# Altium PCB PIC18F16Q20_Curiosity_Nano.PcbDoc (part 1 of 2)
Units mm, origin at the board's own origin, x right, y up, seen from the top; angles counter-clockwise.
Board outline 50.8 x 20.32 mm, 4 copper layers (Top Layer, Gnd Plane, Pwr Plane, Bottom Layer), stack 1.574 mm thick; 77 components, 73 nets, 345 pads, 157 vias.
Unrouted connection lines stored in the file: 1.
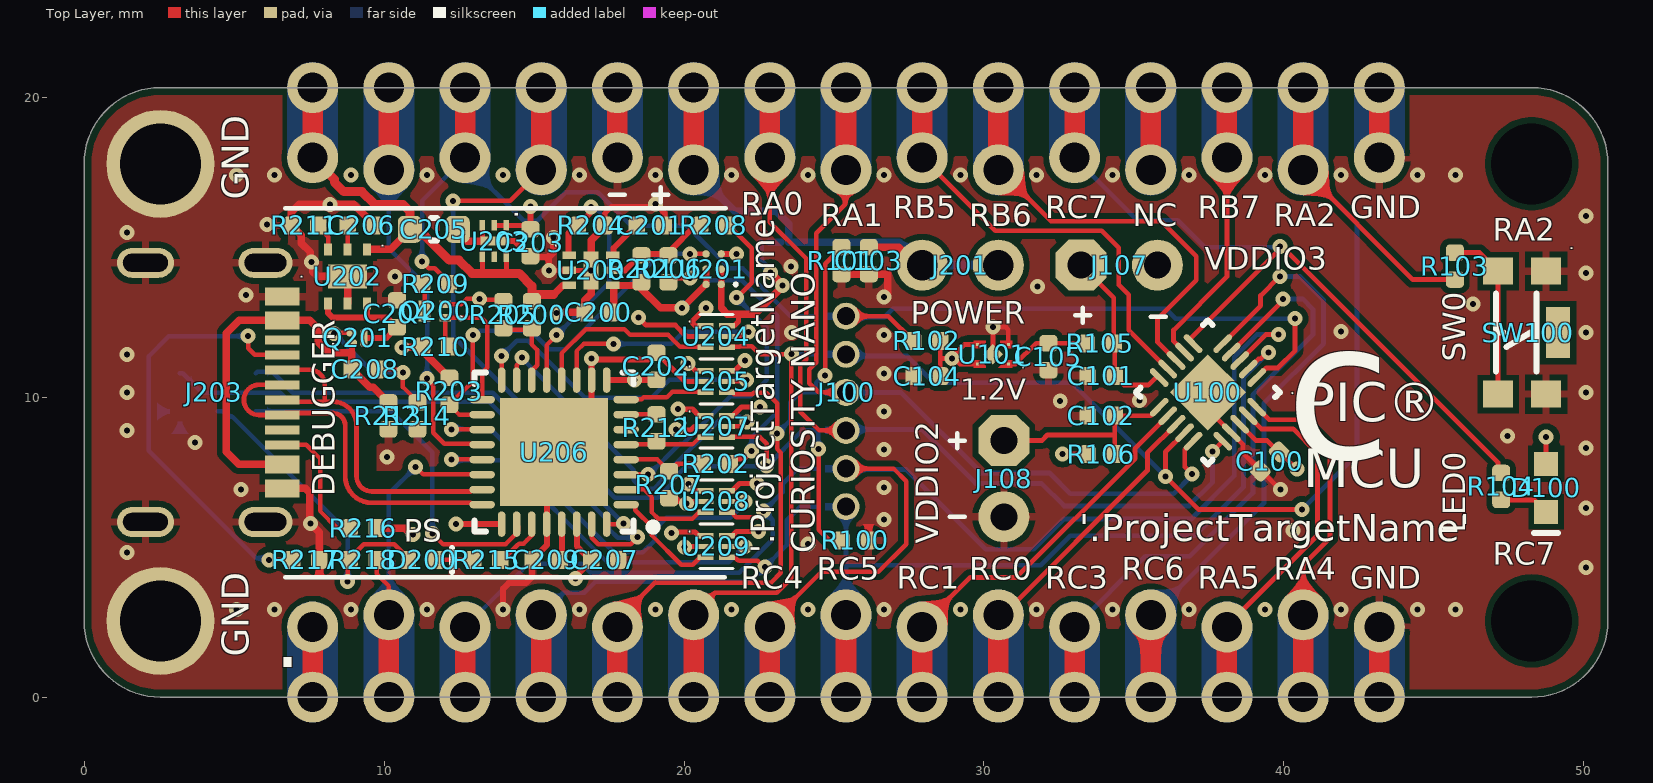
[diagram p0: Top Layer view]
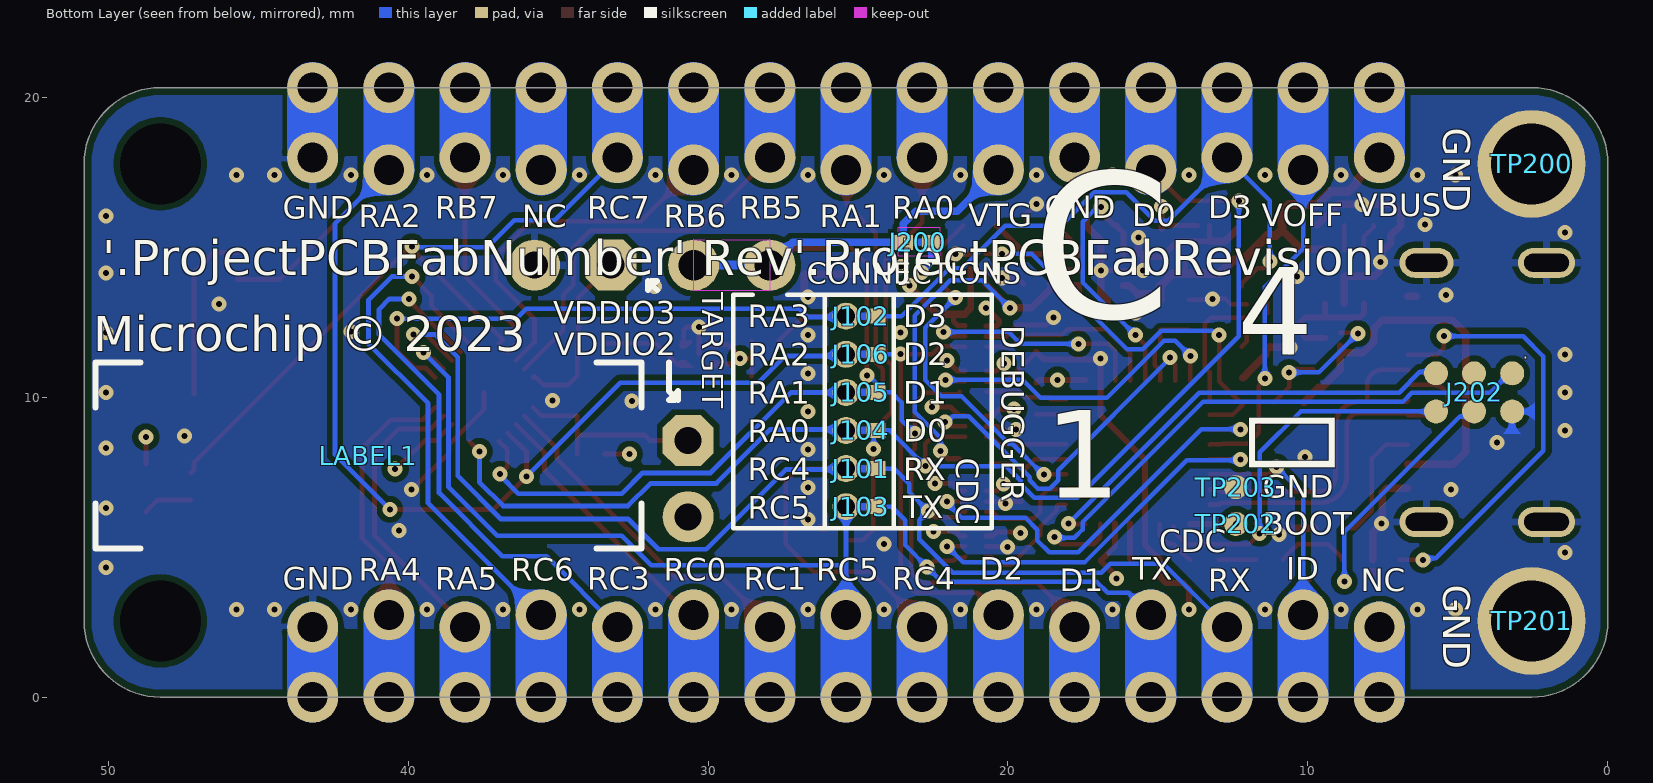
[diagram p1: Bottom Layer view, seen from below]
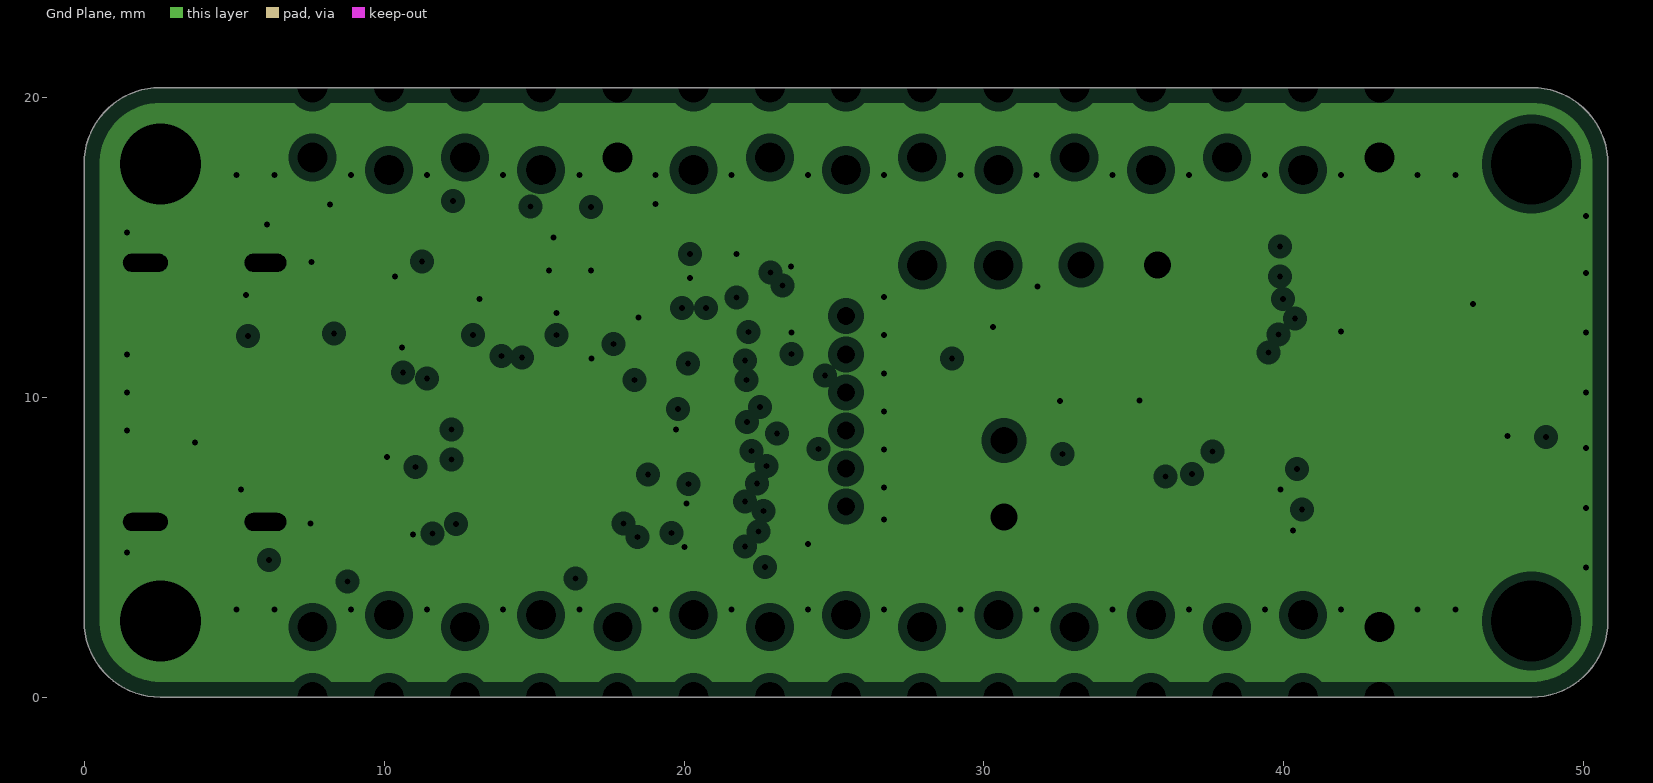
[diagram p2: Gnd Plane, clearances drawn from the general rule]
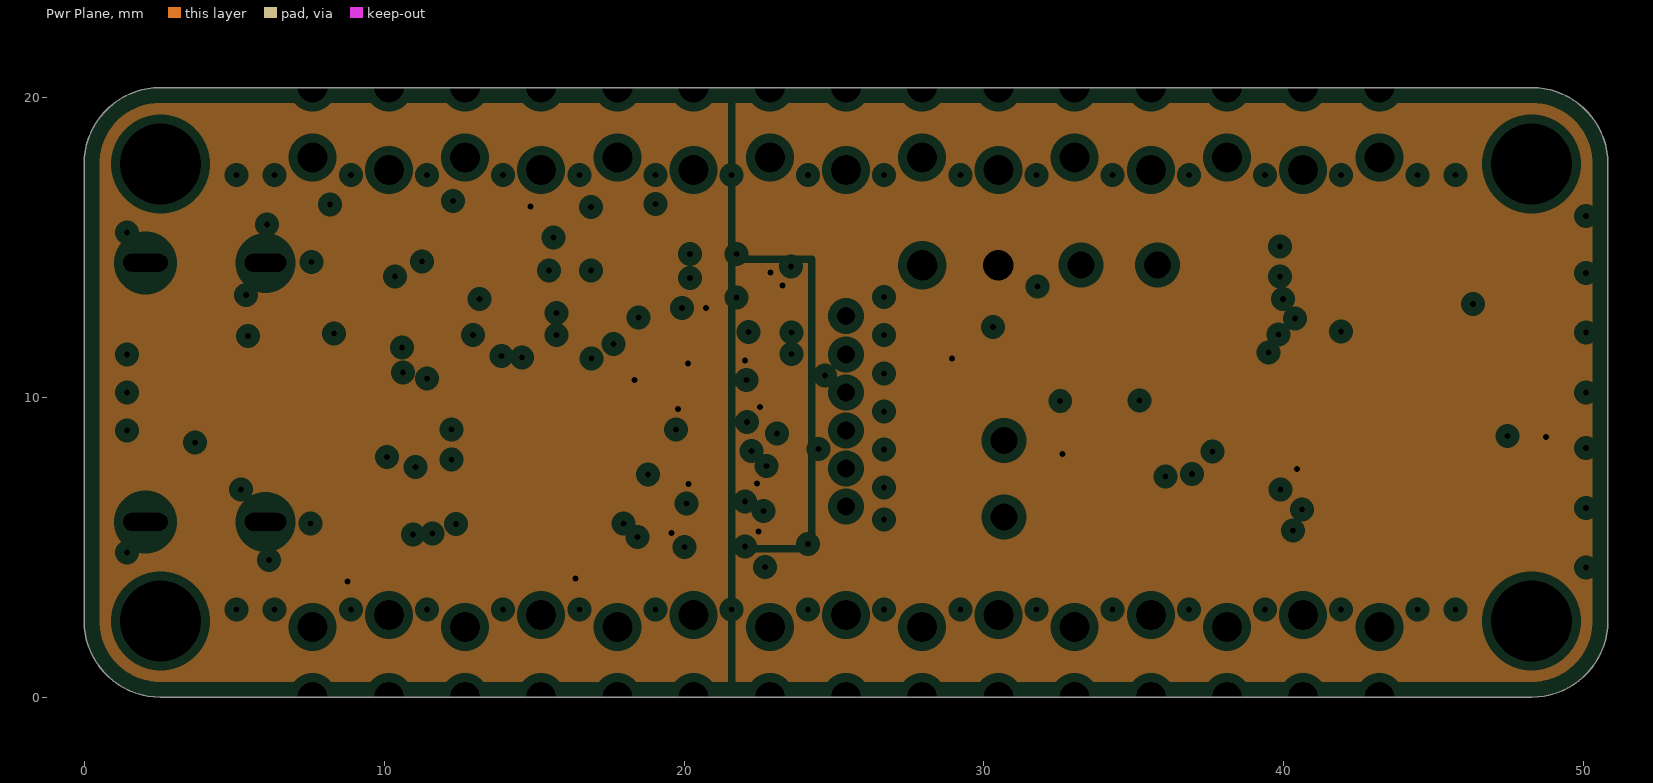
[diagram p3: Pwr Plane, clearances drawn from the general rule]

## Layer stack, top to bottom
Top Solder: solder mask 0.01, Solder Resist, Dk 3.5
Top Layer: signal copper 0.035
Dielectric 1: prepreg 0.1168, PP-016, Dk 4.4
Gnd Plane: plane copper 0.035, net GND
Dielectric2: core 1.2, FR-4, Dk 4.2
Pwr Plane: plane copper 0.035, net (Multiple Nets)
Dielectric 3: prepreg 0.1168, PP-016, Dk 4.4
Bottom Layer: signal copper 0.035
Bottom Solder: solder mask 0.01, Solder Resist, Dk 3.5

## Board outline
0,2.54 0,17.78 cw(c2.54,17.78) 2.54,20.32 48.26,20.32 cw(c48.26,17.78) 50.8,17.78 50.8,2.54 cw(c48.26,2.54) 48.26,0 2.54,0 cw(c2.54,2.54)

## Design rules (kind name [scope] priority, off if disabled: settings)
AcuteAngle [All] p1: minimum=8.00000000000000E+0001 checktracksonly=FALSE
AssemblyTestPointUsage [All] p1: valid=2 allowmultiple=TRUE
AssemblyTestpoint CNANO_Testpoints [HasCompParameterValue('MCHP-ID','CON2115') Or HasCompParameterValue('MCHP-ID','CON2119') Or HasCompParameterValue('MCHP-ID','CON2120')] p1: testpointundercomponent=TRUE minsize=0.8 maxsize=2.54 preferedsize=0.8 minholesize=0 maxholesize=1.27 preferedholesize=0.25 testpointgrid=0.025 usegrid=FALSE gridtolerance=0 allowsidebottom=TRUE minspacing=1.27
AssemblyTestpoint [All] p2: testpointundercomponent=FALSE minsize=0.8 maxsize=2.54 preferedsize=0.8 minholesize=0 maxholesize=1.27 preferedholesize=0.25 testpointgrid=0.025 usegrid=FALSE gridtolerance=0 allowsidebottom=TRUE minspacing=1.27 compbodyclearance=1.27
BoardOutlineClearance BoardOutlineClearance_edge_connector [InComponent('J100')] p1: gap=0 ignorepadtopadclearanceinfootprint=FALSE
BoardOutlineClearance BoardOutlineClearance_LAYERNAME [IsText and (X1 >= 100) and (Y1 <= -60)] p2: gap=0 ignorepadtopadclearanceinfootprint=FALSE
BoardOutlineClearance [All] p3: gap=0.25 ignorepadtopadclearanceinfootprint=FALSE
Clearance Clearance_Poly_Impedance [IsRegion vs InDifferentialPairClass('All Differential Pairs')] p1: gap=0.6 ignorepadtopadclearanceinfootprint=FALSE
Clearance Clearance_Poly [InPoly] p2: gap=0.2 ignorepadtopadclearanceinfootprint=FALSE
Clearance [All] p3: gap=0.15 ignorepadtopadclearanceinfootprint=FALSE except(0.3: Arc-Hole Track-Hole SMDPad-Hole THPad-Hole Via-Hole Fill-Hole Poly-Hole Region-Hole Text-Hole)
ComponentClearance ComponentClearance_EDGE [InComponent('J100')] p1: gap=0 collisioncheckmode=3 verticalgap=0 showdistances=FALSE
ComponentClearance [All] p2: gap=0.254 collisioncheckmode=3 verticalgap=0.254 showdistances=TRUE donotcheckwithout3dbody=TRUE
DiffPairsRouting [All] p1: maxlimit=0.22 minlimit=0.22 mostfreqgap=0.22 toplayer_minwidth=0.16 toplayer_maxwidth=0.16 toplayer_prefwidth=0.16 bottomlayer_minwidth=0.16 bottomlayer_maxwidth=0.16 bottomlayer_prefwidth=0.16 maxuncoupledlength=5
FabricationTestPointUsage TestPointUsage [All] p1 off: valid=2 allowmultiple=TRUE
FabricationTestpoint Testpoint [All] p1 off: side=2 testpointundercomponent=TRUE minsize=0.8 maxsize=2.54 preferedsize=0.8 minholesize=0 maxholesize=1.27 preferedholesize=0.25 testpointgrid=0 allowsidebottom=TRUE usegrid=FALSE gridtolerance=0 minspacing=1.27
HoleSize [All] p1: absolutevalues=TRUE maxlimit=6.2 minlimit=0.2 maxpercent=80.000 minpercent=20.000
HoleToHoleClearance [All] p1: gap=0.3 allowstackedmicrovias=FALSE
MinimumAnnularRing [All] p1: minimumring=0.15
MinimumSolderMaskSliver LevelShifters [HasCompParameterValue('MCHP-ID','IC1665')] p1: minsoldermaskwidth=0.075
MinimumSolderMaskSliver [All] p2: minsoldermaskwidth=0.08
NetAntennae [Not IsTestpoint] p1: netantennaetolerance=0
PlaneClearance [All] p1: clearance=0.3
PlaneConnect PlaneConnect_MountingHoles [HasPad('TP200-1') OR HasPad('TP201-1')] p1: planeconnectstyle=Direct reliefexpansion=0.508 reliefentries=4 reliefconductorwidth=0.254 reliefairgap=0.254
PlaneConnect [All] p2: pad.planeconnectstyle=Relief pad.reliefexpansion=0.25 pad.reliefentries=4 pad.reliefconductorwidth=0.25 pad.reliefairgap=0.25 via.planeconnectstyle=Direct via.reliefexpansion=0.508 via.reliefentries=4 via.reliefconductorwidth=0.254 via.reliefairgap=0.254
PolygonConnect PolygonConnect_Special [HasPad('TP200-1') OR HasPad('TP201-1') OR HasPad('TP203-1')] p1: connectstyle=Direct reliefconductorwidth=0.254 reliefentries=4 polygonreliefangle="90 Angle" airgapwidth=0.254
PolygonConnect [All] p2: thpad.connectstyle=Relief thpad.reliefconductorwidth=0.254 thpad.reliefentries=4 thpad.polygonreliefangle="90 Angle" thpad.airgapwidth=0.2 smdpad.connectstyle=Relief smdpad.reliefconductorwidth=0.254 smdpad.reliefentries=4 smdpad.polygonreliefangle="90 Angle" smdpad.airgapwidth=0.2 via.connectstyle=Direct via.reliefconductorwidth=0.254 via.reliefentries=4 via.polygonreliefangle="90 Angle" via.airgapwidth=0.2
RoutingVias [All] p1: holewidth=0.25 width=0.55 viastyle="Through Hole" minholewidth=0.2 minwidth=0.5 maxholewidth=0.5 maxwidth=1
SMDNeckDown [All] p1: percent=98.000
SilkToSilkClearance SilkToSilkClearance_Text [IsText] p1: silktosilkclearance=0
SilkToSilkClearance [All] p2: silktosilkclearance=0.1
SilkToSolderMaskClearance SilkscreenOverComponentPads_Soldermask [All] p1: minsilkscreentomaskgap=0.12 clearancetoexposedcopper=FALSE
SilkToSolderMaskClearance SilkscreenOverComponentPads_Copper [All] p2: minsilkscreentomaskgap=0.2 clearancetoexposedcopper=TRUE
SolderMaskExpansion SolderMaskTenting [IsVia AND NOT (IsFabTestpoint OR IsAssyTestpoint)] p1: expansion=-1 istentingtop=FALSE
SolderMaskExpansion [All] p2: expansion=0.06 istentingtop=FALSE
UnRoutedNet [All] p1: checkbadconnections=TRUE
ViasUnderSMD ViasUnderSMD_Testpoint [HasPad('TP202-1') OR HasPad('U200-7')] p1: allowed=TRUE
ViasUnderSMD [All] p2: allowed=FALSE
Width [All] p1: maxlimit=10 minlimit=0.125 preferedwidth=0.15 minimp=50.000000 maximp=50.000000 favimp=50.000000
15 further rules are at their usual default settings.

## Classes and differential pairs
component class PIC18F16Q20_Curiosity_Nano_TopLevel: LABEL1 Test1 Test2 "TEST FIXTURE1"
component class S2: C100 C101 C102 C103 C104 C105 D100 J100 J101 J102 J103 J104 J105 J106 J107 J108 R100 R101 R102 R103 R104 R105 R106 SW100 U100 U101
component class S1: C200 C201 C202 C203 C204 C205 C206 C207 C208 C209 D200 J200 J201 J202 J203 Q200 Q201 R200 R201 R202 R203 R204 R205 R206 R207 R208 R209 R210 R211 R212 R213 R214 R215 R216 R217 R218 TP200 TP201 TP202 TP203 U200 U201 U202 U203 U204 U205 U206 U207 U208 U209
net class Power: GND VCC_EDGE VCC_LEVEL VCC_P3V3 VCC_REGULATOR VCC_VBUS
differential pair USBD: +USBD_P -USBD_N

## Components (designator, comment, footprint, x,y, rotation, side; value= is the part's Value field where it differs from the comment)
C100 "Capacitor NP" CAP_C_0402#1 39.522,7.857 r225 top value=0.1uF
C101 "Capacitor NP" CAP_C_0402#1 33.908,10.713 r180 top value=0.1uF
C102 "Capacitor NP" CAP_C_0402#1 33.917,9.382 r180 top value=0.1uF
C103 "Capacitor NP" CAP_C_0402#1 26.162,14.554 r90 top locked value=2.2uF
C104 "Capacitor NP" CAP_C_0402#2 28.105,10.701 r0 top value=1uF
C105 "Capacitor NP" CAP_C_0402#2 32.149,11.35 r90 top value=1uF
C200 "Capacitor NP" CAP_C_0402#1 17.145,12.827 r0 top locked value=2.2uF
C201 "Capacitor NP" CAP_C_0402#1 18.88,15.725 r0 top locked value=0.1uF
C202 "Capacitor NP" CAP_C_0402#1 19.08,11.025 r270 top locked value=0.1uF
C203 "Capacitor NP" CAP_C_0402#1 14.879,15.15 r90 top locked value=2.2uF
C204 "Capacitor NP" CAP_C_0402#1 10.434,12.777 r270 top locked value=2.2uF
C205 "Capacitor NP" CAP_C_0603 11.658,15.597 r180 top locked value=4.7uF
C206 "Capacitor NP" CAP_C_0402#1 9.235,15.725 r180 top locked value=2200pF
C207 "Capacitor NP" CAP_C_0402#1 17.355,4.575 r0 top locked value=0.1uF
C208 "Capacitor NP" CAP_C_0402#1 9.368,10.931 r180 top locked value=0.1uF
C209 "Capacitor NP" CAP_C_0402#1 15.405,4.575 r0 top locked value=1uF
D100 "LED_yellow" LED_0603_Yellow 48.74,6.975 r270 top value="Yellow LED"
D200 "LED_green" LED_0402_GREEN 11.265,4.575 r0 top locked value="LED SINGLE SML-P12MTT86R YELLOW-GREEN"
J100 "CON EDGE CNANO-30" CON_EDGE_CNANO-30 7.62,10.16 r0 top locked value="EDGE 30P Female CNANO"
J101 "CON JMPR LINK CLOSED" CON_JMPR_0402_PCB_TRACE_LINK_0.9mm_PAD_0.6mm_PTH 24.875,7.62 r0 bottom locked net-tie value="CON JMPR LINK CLOSED_0.9mm TH PAD"
J102 "CON JMPR LINK CLOSED" CON_JMPR_0402_PCB_TRACE_LINK_0.9mm_PAD_0.6mm_PTH 24.875,12.7 r0 bottom locked net-tie value="CON JMPR LINK CLOSED_0.9mm TH PAD"
J103 "CON JMPR LINK CLOSED" CON_JMPR_0402_PCB_TRACE_LINK_0.9mm_PAD_0.6mm_PTH 24.875,6.35 r0 bottom locked net-tie value="CON JMPR LINK CLOSED_0.9mm TH PAD"
J104 "CON JMPR LINK CLOSED" CON_JMPR_0402_PCB_TRACE_LINK_0.9mm_PAD_0.6mm_PTH 24.875,8.89 r0 bottom locked net-tie value="CON JMPR LINK CLOSED_0.9mm TH PAD"
J105 "CON JMPR LINK CLOSED" CON_JMPR_0402_PCB_TRACE_LINK_0.9mm_PAD_0.6mm_PTH 24.875,10.16 r0 bottom locked net-tie value="CON JMPR LINK CLOSED_0.9mm TH PAD"
J106 "CON JMPR LINK CLOSED" CON_JMPR_0402_PCB_TRACE_LINK_0.9mm_PAD_0.6mm_PTH 24.875,11.43 r0 bottom locked net-tie value="CON JMPR LINK CLOSED_0.9mm TH PAD"
J107 "Header 1x2" HDR_M_2.54_1x2 34.512,14.402 r0 top value="HDR-2.54 Male 1x2"
J108 "Header 1x2" HDR_M_2.54_1x2 30.663,7.282 r270 top value="HDR-2.54 Male 1x2"
J200 "CON JMPR LINK CLOSED" CON_JMPR_0402_PCB_TRACE_LINK 23.015,15.162 r0 bottom locked net-tie value="CON 0402 PCB TRACE LINK"
J201 "CON JMPR LINK CLOSED" CON_JMPR_2.54_1x2_TH_PCB_TRACE_LINK 29.21,14.402 r0 top locked net-tie value="CON JMPR 1x2 PCB TRACE LINK"
J202 "TP ARRAY NO BOM" TESTPOINT_ARRAY_2x3_1.27mm_pitch_SMD 4.46,10.16 r0 bottom locked value="TESTPOINT ARRAY 2x3 JTAG"
J203 "CON USB2.0-C RCPT SMD RA KLS KLS1-5409" CON_USB2.0-C_RCPT_SMD_RA_KLS_KLS1-5409 3.4,10.16 r270 top locked value="USB2.0 Type-C FEMALE"
LABEL1 "08-10015" 08-10015 41.325,8.05 r180 bottom locked value="PCBA LABEL 18X6mm"
Q200 "Transistor MOS-N GSD" X1-DFN1006-3 11.69,12.875 r180 top locked value=DMN65D8LFB-7B
Q201 "Transistor MOS-P GSD" LGA-3_GSD_0.7x0.6_CSD25501F3 9.102,11.975 r0 top locked value=CSD25501F3
R100 "Resistor" RES_C_0402 25.705,5.228 r0 top locked value=47k
R101 "Resistor" RES_C_0402 25.248,14.554 r270 top locked value=47k
R102 "Resistor" RES_C_0402 28.089,11.875 r0 top value=47k
R103 "Resistor" RES_C_0402 45.7,14.371 r90 top value=1k
R104 "Resistor" RES_C_0402 47.244,7.023 r270 top value=1k
R105 "Resistor" RES_C_0402 33.879,11.797 r180 top value=0R
R106 "Resistor" RES_C_0402 33.908,8.105 r180 top value=0R
R200 "Resistor" RES_C_0402 14.929,12.75 r270 top locked value=47k
R201 "Resistor" RES_C_0402 18.58,14.275 r90 top locked value=47k
R202 "Resistor" RES_C_0402 21.079,7.775 r0 top locked value=47k
R203 "Resistor" RES_C_0402 12.175,10.194 r90 top locked value=47k
R204 "Resistor" RES_C_0402 16.905,15.725 r0 top locked value=47k
R205 "Resistor" RES_C_0402 13.979,12.75 r270 top locked value=47k
R206 "Resistor" RES_C_0402 19.48,14.275 r90 top locked value=27k
R207 "Resistor" RES_C_0402 19.505,7.079 r90 top locked value=47k
R208 "Resistor" RES_C_0402 20.992,15.725 r0 top locked value=33k
R209 "Resistor" RES_C_0402 11.715,13.775 r0 top locked value=1k
R210 "Resistor" RES_C_0402 11.715,11.684 r180 top locked value=47k
R211 "Resistor" RES_C_0402 7.363,15.725 r180 top locked value=470R
R212 "Resistor" RES_C_0402 19.08,8.974 r90 top locked value=1k
R213 "Resistor" RES_C_0402 10.144,9.375 r270 top locked value=47k
R214 "Resistor" RES_C_0402 11.11,9.375 r270 top locked value=47k
R215 "Resistor" RES_C_0402 13.43,4.575 r0 top locked value=1k
R216 "Resistor" RES_C_0402 9.302,5.633 r0 top locked value=5.1k
R217 "Resistor" RES_C_0402 7.394,4.575 r0 top locked value=5.1k
R218 "Resistor" RES_C_0402 9.298,4.575 r180 top locked value=1k
SW100 "Switch 4 Pin" SW_TACT_SMD_KLS_L-KLS7-TS0304A-2-300-T 47.915,12.15 r270 top locked value="TACT SPST"
TP200 "Test Point No BOM" TP_3.6X2.7 2.54,17.78 r90 bottom locked value="TP TH D3.6H2.7"
TP201 "Test Point No BOM" TP_3.6X2.7 2.54,2.54 r90 bottom locked value="TP TH D3.6H2.7"
TP202 "Test Point No BOM" CON_TP_0.8dia_SMD_with_Test_Jig_Layer 12.4,5.777 r180 bottom locked value="TP SMD D0.8"
TP203 "Test Point No BOM" CON_TP_0.8dia_SMD_with_Test_Jig_Layer 12.4,7 r180 bottom locked value="TP SMD D0.8"
U100 "PIC18F16Q20 T-I/REB" VQFN-20_3X3_EP1.8x1.8 37.465,10.16 r225 top locked value=PIC18F16Q20
U101 "MCP1711 UQFN-4" UQFN-4_1x1_EP0.48x0.48 30.297,11.433 r90 top value=MCP1711/1.2V
U200 "MIC53XX ADJ MLF-6" "MLF-6 1.6X1.6mm" 16.905,14.225 r0 top locked value=MIC5353YMT-TR
U201 "MIC94163_1.5MM_1MM" MIC94163_1.5MM_1MM 21.013,14.267 r180 top locked value=MIC94163YCS
U202 "MIC2008YML-TR VDFN-6" VDFN-6_2x2_EP0.8X1.40 8.785,14.028 r270 top locked value=MIC2008
U203 "MIC5528MT DFN-6" DFN-6_1.2x1.2 13.679,15.2 r180 top locked value="MIC5528 3V3"
U204 "74LVC(H)1T45 SOT-23-6_SC-70-6_SOT-6_SOT-363_DSBGA" X2-DFN1010-6 21.079,12.025 r0 top value=74LVC1T45FW4-7
U205 "74LVC(H)1T45 SOT-23-6_SC-70-6_SOT-6_SOT-363_DSBGA" X2-DFN1010-6 21.079,10.525 r0 top value=74LVC1T45FW4-7
U206 "SAMD21E QFN-32" QFN-32_5X5_EP3.6x3.6_L 15.67,8.17 r180 top locked value=ATSAMD21E18
U207 "74LVC(H)1T45 SOT-23-6_SC-70-6_SOT-6_SOT-363_DSBGA" X2-DFN1010-6 21.079,9.025 r0 top value=74LVC1T45FW4-7
U208 "74LVC(H)1T45 SOT-23-6_SC-70-6_SOT-6_SOT-363_DSBGA" X2-DFN1010-6 21.079,6.525 r0 top value=74LVC1T45FW4-7
U209 "74LVC(H)1T45 SOT-23-6_SC-70-6_SOT-6_SOT-363_DSBGA" X2-DFN1010-6 21.079,5.025 r0 top value=74LVC1T45FW4-7

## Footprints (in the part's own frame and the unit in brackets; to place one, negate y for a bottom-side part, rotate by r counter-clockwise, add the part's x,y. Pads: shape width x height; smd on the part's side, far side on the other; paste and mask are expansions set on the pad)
08-10015 [mm]
  silkscreen extent -9.1,-3.1 9.1,3.1, body extent -9.04,-2.97 8.96,3.03, height 0.1
CAP_C_0402#1 [mm] "Chip Capacitor, 2-Leads, Body 1.0x0.5mm, IPC High Density"
  rrect50% 0.55x0.6 smd: 1(-0.45,0) 2(0.45,0)
  body extent -0.5,-0.3 0.5,0.3, height 0.2
CAP_C_0402#2 [mm] "Chip Capacitor, 2-Leads, Body 1.0x0.5mm, IPC High Density"
  rrect50% 0.55x0.6 smd paste-1: 1(-0.45,0) 2(0.45,0)
  body extent -0.5,-0.3 0.5,0.3, height 0.2
CAP_C_0603 [mm] "Chip Capacitor, 2-Leads, Body 1.6x0.8mm, IPC Medium Density"
  rrect50% 0.8x0.9 smd: 1(-0.8,0) 2(0.8,0)
  silkscreen extent -0.1,-0.38 0.1,0.38, body extent -0.8,-0.4 0.8,0.4, height 0.65
CON_EDGE_CNANO-30 [mil]
  round 67 hole 39.37 mask+3.94: 1(0,-400) 1(0,-308) 2(100,-400) 2(100,-292) 3(200,-400) 3(200,-308) 4(300,-400) 4(300,-292) 5(400,-400) 5(400,-308) 6(500,-400) 6(500,-292) 7(600,-400) 7(600,-308) 8(700,-400) 8(700,-292) 9(800,-400) 9(800,-308) 10(900,-400) 10(900,-292) 11(1000,-400) 11(1000,-308) 12(1100,-400) 12(1100,-292) 13(1200,-400) 13(1200,-308) 14(1300,-400) 14(1300,-292) 15(1400,-400) 15(1400,-308) 16(1400,308) 16(1400,400) 17(1300,292) 17(1300,400) 18(1200,308) 18(1200,400) 19(1100,292) 19(1100,400) 20(1000,308) 20(1000,400) 21(900,292) 21(900,400) 22(800,308) 22(800,400) 23(700,292) 23(700,400) 24(600,308) 24(600,400) 25(500,292) 25(500,400) 26(400,308) 26(400,400) 27(300,292) 27(300,400) 28(200,308) 28(200,400) 29(100,292) 29(100,400) 30(0,308) 30(0,400)
  Top Layer lines w27: 0,-400 0,-308 ; 0,308 0,400 ; 100,-400 100,-292 ; 100,292 100,400 ; 200,-400 200,-308 ; 200,308 200,400 ; 300,-400 300,-292 ; 300,292 300,400 ; 400,-400 400,-308 ; 400,308 400,400 ; 500,-400 500,-292 ; 500,292 500,400 ; 600,-400 600,-308 ; 600,308 600,400 ; 700,-400 700,-292 ; 700,292 700,400 ; 800,-400 800,-308 ; 800,308 800,400 ; 900,-400 900,-292 ; 900,292 900,400 ; 1000,-400 1000,-308 ; 1000,308 1000,400 ; 1100,-400 1100,-292 ; 1100,292 1100,400 ; 1200,-400 1200,-308 ; 1200,308 1200,308.66 1200,400 ; 1300,-400 1300,-292 ; 1300,292 1300,400 ; 1400,-400 1400,-308 ; 1400,308 1400,400
  Bottom Layer lines w67: 0,-400 0,-308 ; 0,308 0,400 ; 100,-400 100,-292 ; 100,292 100,400 ; 200,-400 200,-308 ; 200,308 200,400 ; 300,-400 300,-292 ; 300,292 300,400 ; 400,-400 400,-308 ; 400,308 400,400 ; 500,-400 500,-292 ; 500,292 500,400 ; 600,-400 600,-308 ; 600,308 600,400 ; 700,-400 700,-292 ; 700,292 700,400 ; 800,-400 800,-308 ; 800,308 800,400 ; 900,-400 900,-292 ; 900,292 900,400 ; 1000,-400 1000,-308 ; 1000,308 1000,400 ; 1100,-400 1100,-292 ; 1100,292 1100,400 ; 1200,-400 1200,-308 ; 1200,308 1200,400 ; 1300,-400 1300,-292 ; 1300,292 1300,400 ; 1400,-400 1400,-308 ; 1400,308 1400,400
  Multi-Layer pour cut-out: 1440,310 1440,450 -40,450 -40,310
  Multi-Layer pour cut-out: -40,-310 -40,-450 1440,-450 1440,-310
CON_JMPR_2.54_1x2_TH_PCB_TRACE_LINK [mm]
  round 1.7 hole 1.02: 1(-1.27,0) 2(1.27,0)
  Bottom Layer lines w0.3: -1.27,0 1.27,0
CON_JMPR_0402_PCB_TRACE_LINK [mm]
  rect 0.65x0.5 smd paste-1: 1(-0.475,0) 2(0.475,0)
  Top Layer lines w0.254: -0.175,0 0.2,0
CON_JMPR_0402_PCB_TRACE_LINK_0.9mm_PAD_0.6mm_PTH [mm]
  rect 0.65x0.5 smd paste-1: 1(-0.475,0)
  round 0.9 hole 0.6 paste-1: 2(0.525,0)
  Top Layer region: -0.175,0.125 0.175,0.125 0.175,-0.125 -0.175,-0.125
CON_TP_0.8dia_SMD_with_Test_Jig_Layer [mil]
  round 31.5 smd paste-39.37: 1(0,0)
CON_USB2.0-C_RCPT_SMD_RA_KLS_KLS1-5409 [mm]
  rrect50% 1x1.8 on Top Paste: 0(-4.32,2.645) 0(4.32,2.645)
  rrect50% 1x1.9 on Top Paste: 0(-4.32,-1.355) 0(4.32,-1.355)
  oval 1x1.8 hole 0.6 slot 1.4 at 90 deg: 1(-4.32,2.645) 2(4.32,2.645)
  oval 1x1.9 hole 0.6 slot 1.5 at 90 deg: 3(-4.32,-1.355) 4(4.32,-1.355)
  rect 0.6x1.15 smd: A1/B12(-3.2,3.21) A4/B9(-2.4,3.21) B1/A12(3.2,3.21) B4/A9(2.4,3.21)
  rect 0.3x1.15 smd: A5(-1.25,3.21) A6(-0.25,3.21) A7(0.25,3.21) A8(1.25,3.21) B5(1.75,3.21) B6(0.75,3.21) B7(-0.75,3.21) B8(-1.75,3.21)
  body extent -4.47,-3.46 4.47,3.45, height 3.26
DFN-6_1.2x1.2 [mm] "DFN, 6-Leads, Body 1.2x1.2mm (max), Pitch 0.65"
  rect 0.18x0.35 smd paste-1 mask+0.05: 1(-0.4,-0.525) 2(0,-0.525) 3(0.4,-0.525) 4(0.4,0.525) 5(0,0.525) 6(-0.4,0.525)
  rect 0.94x0.3 smd paste-0.04 mask+0.05: 7(0,0)
  body extent -0.62,-0.62 0.63,0.63, height 0.6
HDR_M_2.54_1x2 [mm] "Header Male Vertical 2 Way 2.54mm Pitch"
  oct 1.7x1.7 hole 0.9: 1(-1.27,0)
  round 1.7 hole 0.9: 2(1.27,0)
  body extent -2.54,-1.27 2.54,1.27, height 5.94
LED_0402_GREEN [mm] "LED chip 0402"
  rect 0.5x0.6 smd: 1(-0.45,0) 2(0.45,0)
  silkscreen extent 1,-0.4 1,0.4, body extent -0.5,-0.3 0.5,0.3, height 0.2
LED_0603_Yellow [mm] "LED chip 0603"
  rect 0.8x0.8 smd: 1(-0.8,0) 2(0.8,0)
  silkscreen extent 1.5,-0.4 1.5,0.4, body extent -0.81,-0.4 0.81,0.4, height 0.6
LGA-3_GSD_0.7x0.6_CSD25501F3 [mm]
  rrect50% 0.25x0.2 on Top Paste: 0(-0.175,-0.2) 0(-0.175,0.2)
  rrect80% 0.35x0.25 smd paste-2539.97 mask-0.05: 1(-0.175,0.175) 2(-0.175,-0.175)
  rrect80% 0.25x0.6 smd paste-0.05 mask-0.05: 3(0.225,0)
  body extent -0.37,-0.32 0.37,0.32, height 0.22
MIC94163_1.5MM_1MM [mm] "6-ball, Body 1.5x1.0mm), Pitch 0.35"
  round 0.25 smd mask+0.05: A1(-0.229,0.508) A2(0.279,0.508) B1(-0.229,0) B2(0.279,0) C1(-0.229,-0.508) C2(0.279,-0.508)
  silkscreen extent -0.76,0.46 -0.66,0.56, body extent -0.5,-0.75 0.5,0.75, height 0.8
"MLF-6 1.6X1.6mm" [mm]
  rect 0.45x0.25 smd mask+0.045: 1(-0.725,0.5) 2(-0.725,0) 3(-0.725,-0.5) 4(0.725,-0.5) 5(0.725,0) 6(0.725,0.5)
  rect 0.5x1.26 smd paste-0.1 mask+0.05: 7(0,0)
  body extent -0.82,-0.8 0.8,0.8, height 0.55
QFN-32_5X5_EP3.6x3.6_L [mm] "QFN, 32-Leads, Body 5.00x5.00mm, Pitch 0.50mm, Thermal Pad 3.60x3.60mm, Least Density"
  oval 0.85x0.25 smd: 1(-2.4,1.75) 2(-2.4,1.25) 3(-2.4,0.75) 4(-2.4,0.25) 5(-2.4,-0.25) 6(-2.4,-0.75) 7(-2.4,-1.25) 8(-2.4,-1.75) 17(2.4,-1.75) 18(2.4,-1.25) 19(2.4,-0.75) 20(2.4,-0.25) 21(2.4,0.25) 22(2.4,0.75) 23(2.4,1.25) 24(2.4,1.75)
  oval 0.25x0.85 smd: 9(-1.75,-2.4) 10(-1.25,-2.4) 11(-0.75,-2.4) 12(-0.25,-2.4) 13(0.25,-2.4) 14(0.75,-2.4) 15(1.25,-2.4) 16(1.75,-2.4) 25(1.75,2.4) 26(1.25,2.4) 27(0.75,2.4) 28(0.25,2.4) 29(-0.25,2.4) 30(-0.75,2.4) 31(-1.25,2.4) 32(-1.75,2.4)
  rect 3.6x3.6 smd paste-5 mask+0: 33(0,0)
  silkscreen extent -3.43,-2.65 2.65,2.65, body extent -2.55,-2.55 2.55,2.55, height 1
RES_C_0402 [mm] "Chip Resistor, 2-Leads, Body 1.0x0.5mm, IPC Medium Density"
  rrect50% 0.55x0.6 smd: 1(-0.45,0) 2(0.45,0)
  body extent -0.5,-0.3 0.5,0.3, height 0.2
SW_TACT_SMD_KLS_L-KLS7-TS0304A-2-300-T [mm]
  rect 0.9x1 smd: 1(-2.05,0.825) 2(2.05,0.825) 3(2.05,-0.775) 4(-2.05,-0.775)
  rect 1.7x0.8 smd: 5(0,1.225)
  silkscreen extent -1.3,-0.85 1.3,0.5, body extent -2.3,-1.43 2.3,1.48, height 1.9
TESTPOINT_ARRAY_2x3_1.27mm_pitch_SMD [mm]
  round 0.8 smd paste-1: 1(-1.27,-0.635) 2(-1.27,0.635) 3(0,-0.635) 4(0,0.635) 5(1.27,-0.635) 6(1.27,0.635)
TP_3.6X2.7 [mm] "Test Point round, diam=3.6mm, drill=2.7mm"
  round 3.6 hole 2.7: 1(0,0)
UQFN-4_1x1_EP0.48x0.48 [mm] "UQGFN 4 Leads Body dimensions L=1 W=1 H=0.6 Exposed Pad 0.48x0.48"
  rect 0.1x0.1 smd mask+0.05: 1(-0.325,-0.513) 2(0.325,-0.513) 3(0.325,0.513) 4(-0.325,0.513)
  rect 0.48x0.48 smd rot 45 mask+0.05: 5(0,0)
  Top Layer region: 0.45,-0.64 0.45,-0.24 0.38,-0.24 0.2,-0.42 0.2,-0.64
  Top Layer region: 0.45,0.64 0.45,0.24 0.38,0.24 0.2,0.42 0.2,0.64
  Top Layer region: -0.45,-0.64 -0.45,-0.17 -0.2,-0.42 -0.2,-0.64
  Top Layer region: -0.45,0.64 -0.45,0.24 -0.38,0.24 -0.2,0.42 -0.2,0.64
  body extent -0.5,-0.5 0.5,0.5, height 0.6
VDFN-6_2x2_EP0.8X1.40 [mm]
  rect 0.36x0.26 on Top Paste: 0(-0.88,0.65) 0(-0.88,0) 0(-0.88,-0.65) 0(0.88,0.65) 0(0.88,0) 0(0.88,-0.65)
  rect 0.6x0.4 on Top Paste: 0(0,0.3) 0(0,-0.3)
  rect 0.4x0.26 smd paste-1: 1(-0.9,0.65) 2(-0.9,0) 3(-0.9,-0.65) 4(0.9,-0.65) 5(0.9,0) 6(0.9,0.65)
  rect 0.8x1.3 smd paste-1: 7(0,0)
  body extent -1,-1 1,1, height 0.9
VQFN-20_3X3_EP1.8x1.8 [mm]
  oval 0.8x0.2 smd mask+0.05: 1(-1.5,0.8) 2(-1.5,0.4) 3(-1.5,0) 4(-1.5,-0.4) 5(-1.5,-0.8) 11(1.5,-0.8) 12(1.5,-0.4) 13(1.5,0) 14(1.5,0.4) 15(1.5,0.8)
  oval 0.2x0.8 smd mask+0.05: 6(-0.8,-1.5) 7(-0.4,-1.5) 8(0,-1.5) 9(0.4,-1.5) 10(0.8,-1.5) 16(0.8,1.5) 17(0.4,1.5) 18(0,1.5) 19(-0.4,1.5) 20(-0.8,1.5)
  rect 1.8x1.8 smd mask+0.05: 21(0,0)
  silkscreen extent -1.7,-1.7 1.7,1.7, body extent -1.5,-1.5 1.5,1.5, height 0.9
X1-DFN1006-3 [mm]
  oval 0.508x0.229 on Top Paste: 0(-0.4,0.25) 0(-0.4,-0.25)
  rect 0.4x0.25 smd paste-1: 1(-0.35,0.225) 2(-0.35,-0.225)
  rect 0.4x0.7 smd: 3(0.35,0)
  silkscreen extent -0.85,0.25 -0.85,0.25, body extent -0.5,-0.3 0.5,0.3, height 0.4
X2-DFN1010-6 [mm] "DFN, 6-Leads, Body 1.0x1.0mm), Pitch 0.35"
  rect 0.535x0.185 smd mask+0.05: 1(-0.357,0.357) 3(-0.357,-0.357) 4(0.357,-0.357) 6(0.357,0.357)
  rect 0.535x0.17 smd mask+0.05: 2(-0.357,0) 5(0.357,0)
  silkscreen extent -0.55,-0.75 0.55,0.74, body extent -0.53,-0.53 0.53,0.53, height 0.4

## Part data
C100 C101 C102 C201 C202 C207 C208: library part CAP1033, Manufacturer 1=Hottech, Manufacturer 2=KEMET, Manufacturer 3="Samsung Electro-Mechanics", Manufacturer 4="Würth Elektronik", Manufacturer 7=Yageo, Manufacturer Part Number 1=C1005B104K160NT, Manufacturer Part Number 2=C0402C104K4RAC7867, Manufacturer Part Number 3=CL05B104KO5NNNC, Manufacturer Part Number 4=885012205037, Manufacturer Part Number 5=CL05B104KO5NNND, Manufacturer Part Number 6=CL05B104KO5NNNO, Manufacturer Part Number 7=CC0402KRX7R7BB104, Operating Temperature="-55C to +125C", Package=0402, Temperature Coefficient=X7R, Tolerance=10%, Voltage=16V
C103 C200 C203 C204: library part CAP1208, Manufacturer 1=Hottech, Manufacturer 2=Murata, Manufacturer 3="Samsung Electro-Mechanics", Manufacturer Part Number 1=C1005A225K100NT, Manufacturer Part Number 2=GRM155R61A225KE95D, Manufacturer Part Number 3=CL05A225KP5NSNC, Operating Temperature="-55C to +85C", Package=0402, Temperature Coefficient=X5R, Tolerance=10%, Voltage=10V
C104 C105 C209: library part CAP0616, Manufacturer 1=KEMET, Manufacturer 2=Hottech, Manufacturer Part Number 1=C0402C105K9PACTU, Manufacturer Part Number 2=C1005A105K6R3NT, Operating Temperature="-55C to +85C", Package=0402, Supplier Part Number 1=399-4873-1-ND, Temperature Coefficient=X5R, Tolerance=10%, Voltage=6.3V
C205: library part CAP0543, Manufacturer 1=KEMET, Manufacturer 2="Taiyo Yuden", Manufacturer 3=Hottech, Manufacturer 4="Samsung Electro-Mechanics", Manufacturer Part Number 1=C0603C475K8PACTU, Manufacturer Part Number 2=LMK107BJ475KA-T, Manufacturer Part Number 3=C1608A475K100NT, Manufacturer Part Number 4=CL10A475KP8NNNC, Operating Temperature="-55C to +85C", Package=0603, Supplier Part Number 1=399-5503-1-ND, Temperature Coefficient=X5R, Tolerance=10%, Voltage=10V
C206: library part CAP1265, Manufacturer 1=KEMET, Manufacturer Part Number 1=C0402C222J3GACTU, Operating Temperature="-55C to +125C", Package=0402, Supplier Part Number 1=399-8957-1-ND, Temperature Coefficient=C0G, Tolerance=5%, Voltage=25V
D100: library part DIODE1547, "LED", Forward Current=20mA, Manufacturer 1="Rohm Semiconductor", Manufacturer Part Number 1=SML-D12Y1WT86, Package=0603, Supplier Part Number 1=SML-D12Y1WT86CT-ND
D200: library part LED1092, "LED", Forward Current=20mA, Manufacturer 1="Rohm Semiconductor", Manufacturer Part Number 1=SML-P12MTT86R, Operating Temperature="-40C to +85C", Package=0402, Power=54mW, Reverse Current=10uA, Reverse Voltage=5V
J100: library part CON2474
J101 J102 J103 J104 J105 J106: library part CON2115
J107 J108: library part CON1632, Current=3A, Manufacturer 1="Würth Elektronik", Manufacturer 2="SHENZHEN JUNHAO ENGINEERING", Manufacturer Part Number 1=61300211121, Manufacturer Part Number 2=R-211-0211-0021-000, Supplier Part Number 1=732-5315-ND, Voltage=250V
J200: library part CON2116
J201: library part CON2118
J202: library part CON2119
J203: library part CON2580, Current=5A, Manufacturer 1="KLS Electronic", Manufacturer Part Number 1=L-KLS1-5409-R, Operating Temperature="-30C to +85C", Voltage="100V AC"
LABEL1: Manufacturer 1="ACT Logimark AS", Manufacturer 2="Sunrise Paper (M) Sdn Bhd", Manufacturer 3=Raynen, Manufacturer Part Number 1=505462, Manufacturer Part Number 2=037268-5, Manufacturer Part Number 3=10010407
Q200: library part TRA1340, "Transistor MOS", Current=260mA, Drain to Source Voltage=60V, Manufacturer 1="Diodes Incorporated", Manufacturer Part Number 1=DMN65D8LFB-7, Manufacturer Part Number 2=DMN65D8LFB-7B, Package=X1-DFN1006-3, Power=430mW, Supplier Part Number 1=DMN65D8LFB-7DITR-ND
Q201: library part TRA1611, "Transistor MOS", Current=-3.6A, Drain to Source Voltage=-20V, Manufacturer 1="Texas Instruments", Manufacturer Part Number 1=CSD25501F3, Manufacturer Part Number 2=CSD25501F3T, Operating Temperature="-55C to +150C", Package=LGA, Supplier Part Number 1=296-51017-2-ND
R100 R101 R102 R200 R201 R202 R203 R204 R205 R207 R210 R213 R214: library part RES2662, Manufacturer 1=Yageo, Manufacturer 2=Hottech, Manufacturer Part Number 1=RC0402FR-0747KL, Manufacturer Part Number 2=RI0402L4702FT, Package=0402, Supplier Part Number 1=311-47.0KLRCT-ND, Tolerance=1%, Voltage=50V
R103 R104 R209 R212 R215 R218: library part RES1022, Manufacturer 1=Panasonic, Manufacturer Part Number 1=ERJ-2RKF1001X, Operating Temperature="-55C to +155C", Package=0402, Power=1/10W, Supplier Part Number 1=P1.00KLTR-ND, Temperature Coefficient=100ppm/C, Tolerance=1%, Voltage=50V
R105 R106: library part RSMT1040, Manufacturer 1=Yageo, Manufacturer 2="Stackpole Electronics Inc", Manufacturer Part Number 1=RC0402JR-070RL, Manufacturer Part Number 2=RMCF0402ZT0R00, Operating Temperature="-55C to +155C", Package=0402, Power=1/16W, Supplier Part Number 1=311-0.0JRCT-ND
R206: library part RES2661, Manufacturer 1=Yageo, Manufacturer 2=Hottech, Manufacturer Part Number 1=RC0402FR-0727KL, Manufacturer Part Number 2=RI0402L2702FT, Package=0402, Supplier Part Number 1=311-27.0KLRCT-ND, Tolerance=1%, Voltage=50V
R208: library part RES1994, Manufacturer 1=Yageo, Manufacturer 2=Hottech, Manufacturer Part Number 1=AC0402FR-0733KL, Manufacturer Part Number 2=RI0402L3302FT, Operating Temperature="-55C to +155C", Package=0402, Power=1/16W, Supplier Part Number 1=YAG3477CT-ND, Temperature Coefficient=100ppm/C, Tolerance=1%
R211: library part RSMT1163, Manufacturer 1=Yageo, Manufacturer Part Number 1=RC0402FR-07470RL, Package=0402, Supplier Part Number 1=311-470LRCT-ND, Tolerance=1%
R216 R217: library part RES1655, Manufacturer 1="Panasonic Electronic Components", Manufacturer Part Number 1=ERJ-2RKF5101X, Operating Temperature="-55C to +155C", Package=0402, Power=1/10W, Supplier Part Number 1=P5.10KLCT-ND, Temperature Coefficient=100ppm/C, Tolerance=1%
SW100: library part SWITCH1170, "Switch", Current=50mA, Manufacturer 1="KLS Electronic", Manufacturer Part Number 1=L-KLS7-TS0304A-2-300-T, Voltage=12V
TP200 TP201: library part CON2131, "Test Point"
TP202 TP203: library part CON2120, "Test Point"
U100: library part MIC9477, Manufacturer 1="Microchip Technology", Manufacturer Part Number 1=PIC18F16Q20T-I/REB, Manufacturer Part Number 2=PIC18F16Q20-I/REB, Operating Temperature="-40°C to +85°C"
U101: library part MIC9478, "LDO MCP1711", Manufacturer 1="Microchip Technology", Manufacturer Part Number 1=MCP1711T-12I/5X, Operating Temperature="-40°C to +85°C"
U200: library part MIC7389, "LDO Regulator", Manufacturer 1="Microchip Technology", Manufacturer Part Number 1=MIC5353YMT-TR, Operating Temperature="-40C to +125C", Supplier Part Number 1=576-3681-1-ND
U201: library part MIC8744, Manufacturer 1="Microchip Technology", Manufacturer Part Number 1=MIC94163YCS-TR, Operating Temperature="-40C to +125C", Supplier Part Number 1=576-4454-2-ND
U202: library part MIC9604, Manufacturer 1="Microchip Technology", Manufacturer Part Number 1=MIC2008YML-TR, Operating Temperature="-40C to +85C", Supplier Part Number 1=576-2591-2-ND
U203: library part MIC6905, Manufacturer 1="Microchip Technology", Manufacturer Part Number 1=MIC5528-3.3YMT-TR, Operating Temperature="-40C to +125C", Supplier Part Number 1=576-4766-1-ND
U204 U205 U207 U208 U209: library part IC1665, Manufacturer 1="Diodes Incorporated", Manufacturer Part Number 1=74LVC1T45FW4-7, Supplier Part Number 1=74LVC1T45FW4-7DICT-ND
U206: library part MIC8641, Manufacturer 1="Microchip Technology", Manufacturer Part Number 1=ATSAMD21E18A-MUT, Operating Temperature="-40C to +85C", Supplier Part Number 1=ATSAMD21E18A-MUTCT-ND

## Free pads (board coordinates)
  oval 0.203x0.483 on Top Paste: 0(13.267,14.603) 0(13.267,15.797) 0(13.679,14.603) 0(13.679,15.797) 0(14.091,14.603) 0(14.091,15.797)
  round 0 hole 2.7 unplated paste-2.6: 0(48.26,2.54) 0(48.26,17.78)

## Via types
v1: diameter 0.5, hole 0.2, Top Layer to Bottom Layer, 147 vias
v2: diameter 0.5, hole 0.2, Top Layer to Bottom Layer, tented both sides, 8 vias
v3: diameter 0.5, hole 0.2, Top Layer to Bottom Layer, tented top, 2 vias

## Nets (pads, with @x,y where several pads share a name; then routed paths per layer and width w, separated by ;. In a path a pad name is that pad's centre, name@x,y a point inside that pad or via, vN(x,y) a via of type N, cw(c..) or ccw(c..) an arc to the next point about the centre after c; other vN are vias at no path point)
BOOT: TP202.1 U206.25 | length 1.5
  Top Layer w0.2: v3(12.4,5.777) U206.25@13.933,5.777
CDC_RX: J100.3 J101.1 U208.4 | length 16.7
  Top Layer w0.15: U208.4@21.429,6.175 21.571,6.175 21.746,6 22.437,6 22.637,6.2 v1(22.655,6.2)
  Bottom Layer w0.15: J100.3@12.7,2.337 14.813,4.45 16.591,4.45 16.891,4.15 21.839,4.15 22.955,5.266 22.955,5.9 v1(22.655,6.2) 23.292,6.837 23.292,7.117 23.795,7.62 J101.1@24.4,7.62 ; J101.1@24.4,7.61 J101.1@24.45,7.61
CDC_RX_CTRL: U206.19 U208.5 | length 14.1
  Top Layer w0.15: v1(12.255,8.925) U206.19@13.28,8.925 ; U208.5@21.429,6.525 v1(22.03,6.525)
  Bottom Layer w0.15: v1(12.255,8.925) 12.266,8.936 13.556,8.936 17.659,4.833 18.629,4.833 19.019,5.223 19.019,5.585 19.409,5.975 21.543,5.975 22.03,6.462 v1(22.03,6.525)
CDC_TX: J100.4 J103.1 U209.4 | length 12.6
  Top Layer w0.15: U209.4@21.429,4.675 21.454,4.65 21.705,4.65 21.793,4.562 21.821,4.562 21.833,4.55 22.451,4.55 22.662,4.34 v1(22.7,4.34)
  Bottom Layer w0.15: J100.4@15.24,2.743 15.972,3.475 16.673,3.475 17.048,3.85 22.211,3.85 v1(22.7,4.34) 23.43,5.069 23.43,5.9 23.88,6.35 J103.1@24.4,6.35
CDC_TX_CTRL: U206.21 U209.5 | length 13
  Top Layer w0.15: v1(12.255,7.925) U206.21@13.28,7.924 ; U209.5@21.429,5.025 v1(22.03,5.025)
  Bottom Layer w0.15: v1(12.255,7.925) 12.286,7.894 14.043,7.894 17.447,4.491 21.496,4.491 v1(22.03,5.025)
DAC: R208.2 U206.3 | length 15.3
  Top Layer w0.15: U206.3@18.06,7.424 v1(18.804,7.424) ; R208.2@21.492,15.725 22.254,14.963 22.254,13.816 v1(21.755,13.317) v1@21.755,13.267
  Bottom Layer w0.15: v1(18.804,7.424) 18.83,7.424 19.856,8.45 19.967,8.45 21.541,10.024 22.204,10.024 22.755,10.575 ; 22.755,10.575 22.755,12.317 ; 22.755,10.575 22.755,12.317 ; 22.755,12.317 v1(21.755,13.317) 22.755,12.317
DBG0: J100.27 J104.1 R100.1 U207.4 | length 29.7
  Top Layer w0.15: v1(12.303,16.548) 14.211,16.548 J100.27@15.24,17.577 ; U207.4@21.429,8.675 22.527,8.675 22.755,8.447 v1(22.755,7.7) ; v1(24.486,8.28) 24.486,5.583 24.841,5.228 R100.1@25.255,5.228
  Bottom Layer w0.15: v1(12.303,16.548) 12.303,12.036 17.69,6.649 19.125,6.649 19.579,7.103 19.579,7.213 20.066,7.7 v1(22.755,7.7) 23.945,8.89 J104.1@24.4,8.89 24.475,8.815 v1@24.475,8.215
DBG0_CTRL: U206.15 U207.5 | length 12.5
  Top Layer w0.15: U206.15@14.416,10.556 U206.15@14.416,10.861 ; U206.15@14.42,10.57 14.42,11.07 14.591,11.241 v1(14.591,11.325) ; U207.5@21.429,9.025 21.872,9.025 22.022,9.175 v1(22.104,9.175)
  Bottom Layer w0.15: v1(14.591,11.325) 14.591,11.306 18.329,7.568 18.329,7.227 18.607,6.949 19.001,6.949 19.279,7.227 19.279,7.338 21.306,9.365 21.841,9.365 22.031,9.175 v1(22.104,9.175)
DBG1: J100.5 J105.1 R101.1 U205.4 | length 21.2
  Top Layer w0.15: J100.5@17.78,2.337 17.78,2.565 19.04,3.825 19.046,3.819 22.904,3.819 23.23,4.145 23.23,5.45 23.23,8.15 23.105,8.275 v1(23.105,8.79) 23.105,9.794 22.749,10.15 22.326,10.15 22.276,10.1 21.68,10.1 U205.4@21.605,10.175 ; v1(24.7,10.728) 24.703,10.731 24.703,14.452 25.248,14.997 R101.1@25.248,15.004
  Bottom Layer w0.15: v1(23.105,8.79) 23.548,9.233 23.548,9.825 23.883,10.16 J105.1@24.4,10.16 24.4,10.485 24.643,10.728 v1(24.7,10.728)
DBG1_CTRL: U205.5 U206.16 | length 20.3
  Top Layer w0.15: U206.16@13.916,10.556 v1(13.916,11.375) ; U205.5@21.429,10.525 v1@22.054,10.525
  Bottom Layer w0.15: 14.421,11.88 v1(13.916,11.375) 14.421,11.88 ; 14.421,11.88 14.8,11.88 ; 14.421,11.88 14.8,11.88 ; 14.8,11.88 16.705,9.975 ; 14.8,11.88 16.705,9.975 ; 16.705,9.975 18.905,9.975 ; 16.705,9.975 18.905,9.975 ; 18.905,9.975 19.505,10.575 ; 18.905,9.975 19.505,10.575 ; 19.505,10.575 v1(22.079,10.575) 19.505,10.575
DBG2: J100.6 J106.1 U204.4 | length 14.3
  Top Layer w0.15: J100.6@20.32,2.743 20.32,2.766 21.029,3.475 23.087,3.475 23.58,3.968 23.58,5.376 v1(23.58,11.435) ; U204.4@21.429,11.675 21.855,11.675 21.88,11.7 22.255,11.7 22.52,11.435 v1@23.555,11.435
  Bottom Layer w0.15: v1@23.555,11.435 v1(23.58,11.435) J106.1@24.4,11.435
DBG2_CTRL: U204.5 U206.11 | length 12.7
  Top Layer w0.15: U206.11@16.416,10.556 16.416,11.537 16.654,11.775 v1(17.655,11.775) ; U204.5@21.429,12.025 21.88,12.025 22.03,12.175 v1(22.154,12.175) v1@22.254,12.175
  Bottom Layer w0.15: 19.571,11.775 v1(17.655,11.775) 19.571,11.775 ; 19.571,11.775 19.971,12.175 ; 19.571,11.775 19.971,12.175 ; 19.971,12.175 v1(22.154,12.175) ; 19.971,12.175 v1(22.154,12.175) ; v1(22.154,12.175) 22.254,12.175 v1(22.154,12.175)
DBG2_GPIO: U204.3 U206.12 | length 6.3
  Top Layer w0.15: U206.12@15.916,10.556 15.916,11.461 16.722,12.267 18.013,12.267 18.205,12.075 19.479,12.075 19.879,11.675 U204.3@20.729,11.675
DBG3: J100.28 J102.1 R209.2 | length 20.1
  Top Layer w0.15: v1(11.265,14.525) 11.49,14.3 11.69,14.3 12.214,13.776 R209.2@12.214,13.7
  Bottom Layer w0.15: v1(11.265,14.525) 11.265,16.548 J100.28@12.7,17.983 12.7,17.834 14.652,15.882 15.107,15.882 16.054,16.829 17.124,16.829 18.234,15.72 20.095,15.72 21.515,14.3 21.951,14.3 23.551,12.7 J102.1@24.4,12.7
DBG3_CTRL: Q200.1 R210.1 U206.17 | length 5.1
  Top Layer w0.15: R210.1@12.215,11.684 12.04,11.859 Q200.1@12.04,12.65 13.242,12.65 13.441,12.451 13.441,10.986 13.28,10.825 U206.17@13.28,9.924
